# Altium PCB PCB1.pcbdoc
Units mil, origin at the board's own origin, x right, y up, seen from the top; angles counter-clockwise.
Board outline 3800 x 2700 mil, 2 copper layers (Top Layer, Bottom Layer), stack 62.2 mil thick; 15 components, 11 nets, 84 pads, 8 vias.
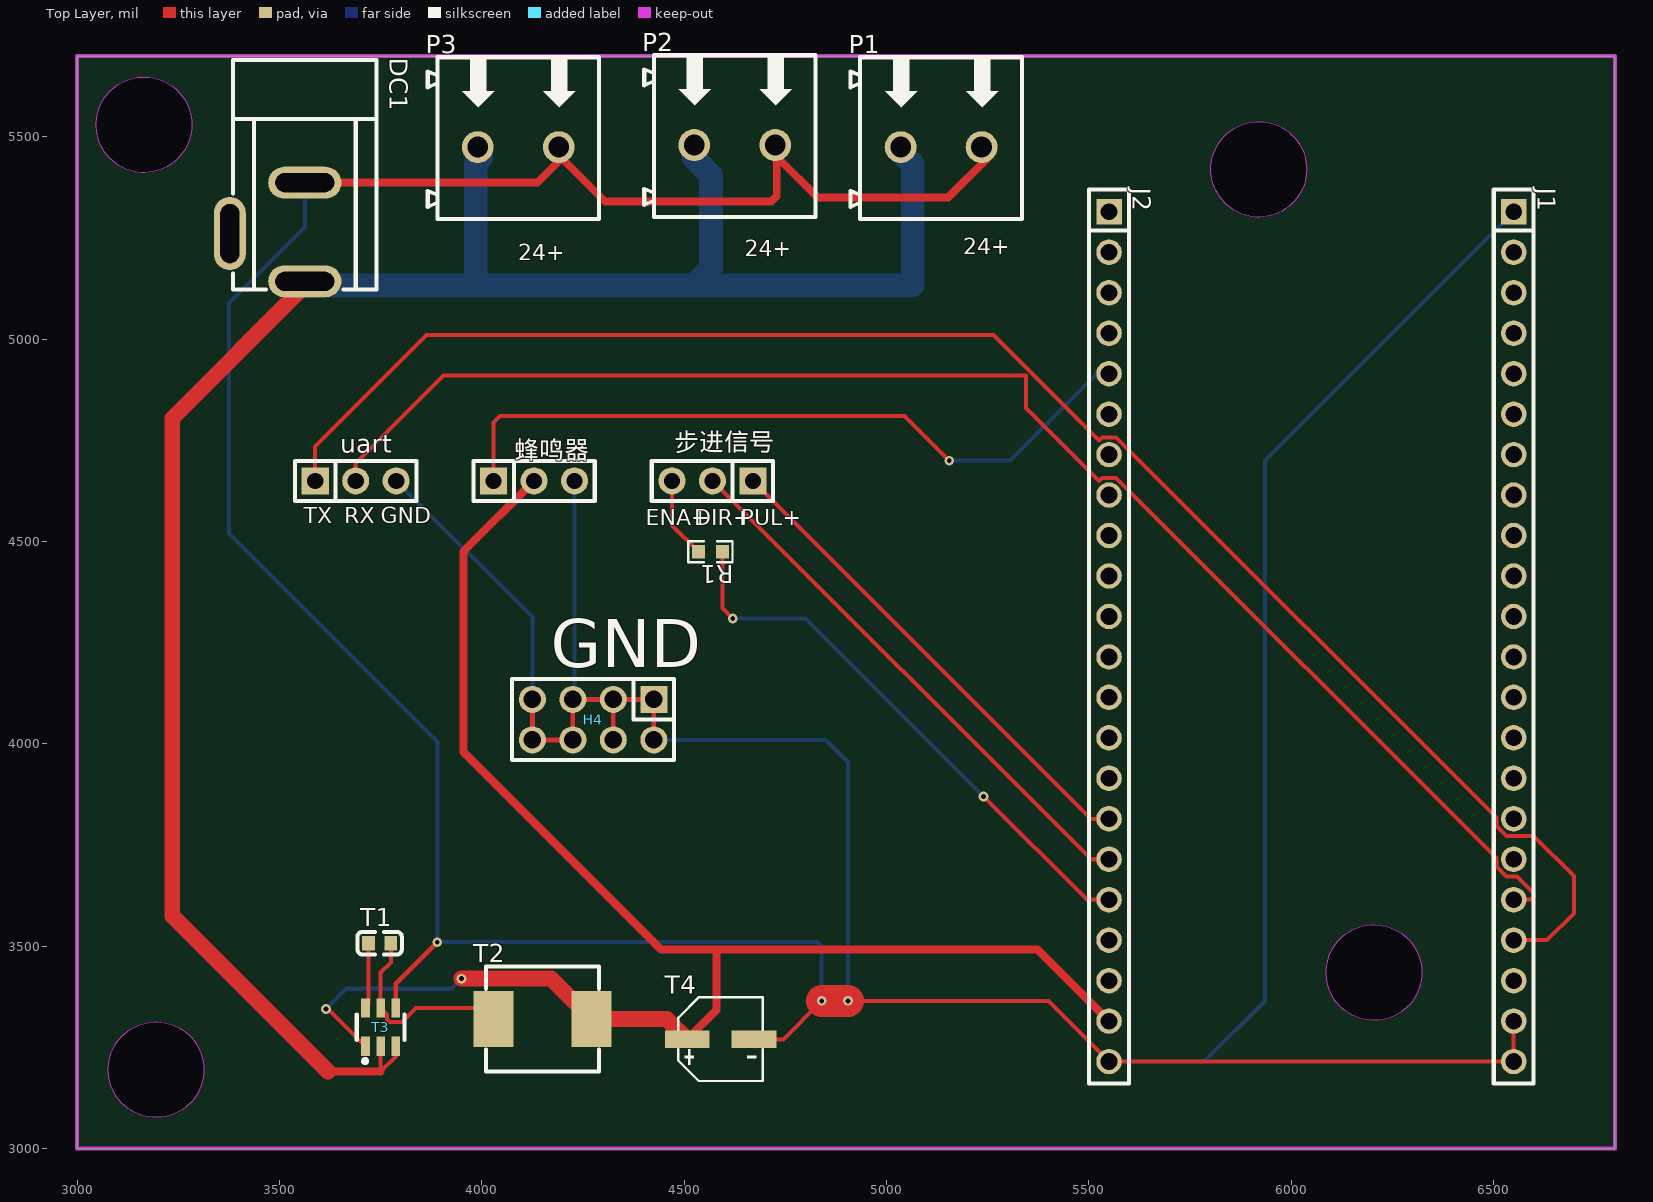
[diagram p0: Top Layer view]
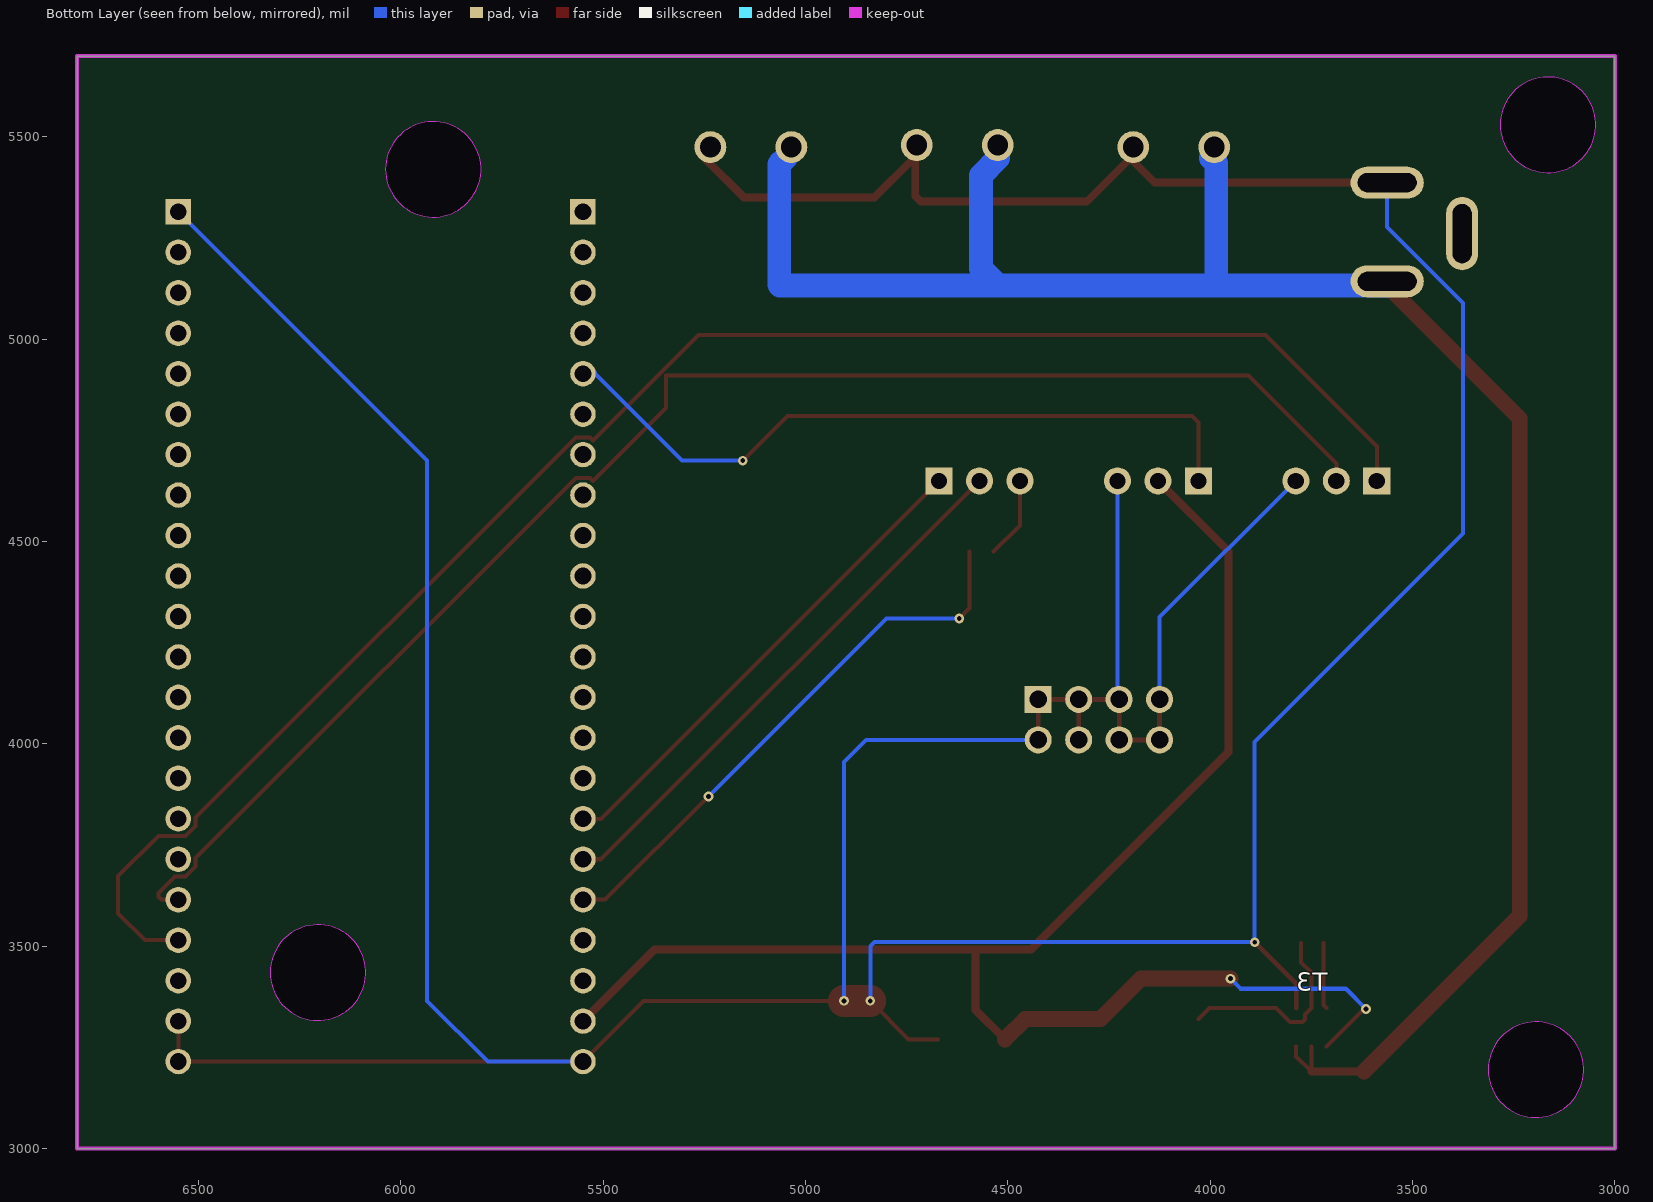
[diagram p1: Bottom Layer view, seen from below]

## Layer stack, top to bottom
Top Solder Mask Layer: solder mask 0.4, Dk 3.3
Top Layer: signal copper 1.4
Dielectric1: surface 59.4, FR4, Dk 4.5
Bottom Layer: signal copper 1.4
Bottom Solder Mask Layer: solder mask 0.4, Dk 3.3

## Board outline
3000,5700 3000,3000 6800,3000 6800,5700
cut-out: 3283.1,5530 3282.7,5520.4 3281.5,5510.8 3279.6,5501.4 3276.9,5492.1 3273.4,5483.1 3269.2,5474.5 3264.4,5466.1 3258.8,5458.3 3252.7,5450.8 3245.9,5444 3238.6,5437.7 3230.9,5432 3222.7,5426.9 3214.1,5422.6 3205.1,5418.9 3196,5416 3186.6,5413.9 3177,5412.5 3167.4,5411.9 3157.8,5412.1 3148.2,5413.1 3138.7,5414.9 3129.4,5417.4 3120.4,5420.7 3111.6,5424.7 3103.2,5429.4 3095.2,5434.7 3087.7,5440.7 3080.6,5447.3 3074.2,5454.5 3068.3,5462.1 3063.1,5470.3 3058.6,5478.8 3054.8,5487.6 3051.7,5496.7 3049.3,5506.1 3047.8,5515.6 3047,5525.2 3047,5534.8 3047.8,5544.4 3049.3,5553.9 3051.7,5563.3 3054.8,5572.4 3058.6,5581.2 3063.1,5589.7 3068.3,5597.9 3074.2,5605.5 3080.6,5612.7 3087.7,5619.3 3095.2,5625.3 3103.2,5630.6 3111.6,5635.3 3120.4,5639.3 3129.4,5642.6 3138.7,5645.1 3148.2,5646.9 3157.8,5647.9 3167.4,5648.1 3177,5647.5 3186.6,5646.1 3196,5644 3205.1,5641.1 3214.1,5637.4 3222.7,5633.1 3230.9,5628 3238.6,5622.3 3245.9,5616 3252.7,5609.2 3258.8,5601.7 3264.4,5593.9 3269.2,5585.5 3273.4,5576.9 3276.9,5567.9 3279.6,5558.6 3281.5,5549.2 3282.7,5539.6
cut-out: 3313.1,3195 3312.7,3185.4 3311.5,3175.8 3309.6,3166.4 3306.9,3157.1 3303.4,3148.1 3299.2,3139.5 3294.4,3131.1 3288.8,3123.3 3282.7,3115.8 3275.9,3109 3268.6,3102.7 3260.9,3097 3252.7,3091.9 3244.1,3087.6 3235.1,3083.9 3226,3081 3216.6,3078.9 3207,3077.5 3197.4,3076.9 3187.8,3077.1 3178.2,3078.1 3168.7,3079.9 3159.4,3082.4 3150.4,3085.7 3141.6,3089.7 3133.2,3094.4 3125.2,3099.7 3117.7,3105.7 3110.6,3112.3 3104.2,3119.5 3098.3,3127.1 3093.1,3135.3 3088.6,3143.8 3084.8,3152.6 3081.7,3161.7 3079.3,3171.1 3077.8,3180.6 3077,3190.2 3077,3199.8 3077.8,3209.4 3079.3,3218.9 3081.7,3228.3 3084.8,3237.4 3088.6,3246.2 3093.1,3254.7 3098.3,3262.9 3104.2,3270.5 3110.6,3277.7 3117.7,3284.3 3125.2,3290.3 3133.2,3295.6 3141.6,3300.3 3150.4,3304.3 3159.4,3307.6 3168.7,3310.1 3178.2,3311.9 3187.8,3312.9 3197.4,3313.1 3207,3312.5 3216.6,3311.1 3226,3309 3235.1,3306.1 3244.1,3302.4 3252.7,3298.1 3260.9,3293 3268.6,3287.3 3275.9,3281 3282.7,3274.2 3288.8,3266.7 3294.4,3258.9 3299.2,3250.5 3303.4,3241.9 3306.9,3232.9 3309.6,3223.6 3311.5,3214.2 3312.7,3204.6
cut-out: 6323.1,3435 6322.7,3425.4 6321.5,3415.8 6319.6,3406.4 6316.9,3397.1 6313.4,3388.1 6309.2,3379.5 6304.4,3371.1 6298.8,3363.3 6292.7,3355.8 6285.9,3349 6278.6,3342.7 6270.9,3337 6262.7,3331.9 6254.1,3327.6 6245.1,3323.9 6236,3321 6226.6,3318.9 6217,3317.5 6207.4,3316.9 6197.8,3317.1 6188.2,3318.1 6178.7,3319.9 6169.4,3322.4 6160.4,3325.7 6151.6,3329.7 6143.2,3334.4 6135.2,3339.7 6127.7,3345.7 6120.6,3352.3 6114.2,3359.5 6108.3,3367.1 6103.1,3375.3 6098.6,3383.8 6094.8,3392.6 6091.7,3401.7 6089.3,3411.1 6087.8,3420.6 6087,3430.2 6087,3439.8 6087.8,3449.4 6089.3,3458.9 6091.7,3468.3 6094.8,3477.4 6098.6,3486.2 6103.1,3494.7 6108.3,3502.9 6114.2,3510.5 6120.6,3517.7 6127.7,3524.3 6135.2,3530.3 6143.2,3535.6 6151.6,3540.3 6160.4,3544.3 6169.4,3547.6 6178.7,3550.1 6188.2,3551.9 6197.8,3552.9 6207.4,3553.1 6217,3552.5 6226.6,3551.1 6236,3549 6245.1,3546.1 6254.1,3542.4 6262.7,3538.1 6270.9,3533 6278.6,3527.3 6285.9,3521 6292.7,3514.2 6298.8,3506.7 6304.4,3498.9 6309.2,3490.5 6313.4,3481.9 6316.9,3472.9 6319.6,3463.6 6321.5,3454.2 6322.7,3444.6
cut-out: 6038.1,5420 6037.7,5410.4 6036.5,5400.8 6034.6,5391.4 6031.9,5382.1 6028.4,5373.1 6024.2,5364.5 6019.4,5356.1 6013.8,5348.3 6007.7,5340.8 6000.9,5334 5993.6,5327.7 5985.9,5322 5977.7,5316.9 5969.1,5312.6 5960.1,5308.9 5951,5306 5941.6,5303.9 5932,5302.5 5922.4,5301.9 5912.8,5302.1 5903.2,5303.1 5893.7,5304.9 5884.4,5307.4 5875.4,5310.7 5866.6,5314.7 5858.2,5319.4 5850.2,5324.7 5842.7,5330.7 5835.6,5337.3 5829.2,5344.5 5823.3,5352.1 5818.1,5360.3 5813.6,5368.8 5809.8,5377.6 5806.7,5386.7 5804.3,5396.1 5802.8,5405.6 5802,5415.2 5802,5424.8 5802.8,5434.4 5804.3,5443.9 5806.7,5453.3 5809.8,5462.4 5813.6,5471.2 5818.1,5479.7 5823.3,5487.9 5829.2,5495.5 5835.6,5502.7 5842.7,5509.3 5850.2,5515.3 5858.2,5520.6 5866.6,5525.3 5875.4,5529.3 5884.4,5532.6 5893.7,5535.1 5903.2,5536.9 5912.8,5537.9 5922.4,5538.1 5932,5537.5 5941.6,5536.1 5951,5534 5960.1,5531.1 5969.1,5527.4 5977.7,5523.1 5985.9,5518 5993.6,5512.3 6000.9,5506 6007.7,5499.2 6013.8,5491.7 6019.4,5483.9 6024.2,5475.5 6028.4,5466.9 6031.9,5457.9 6034.6,5448.6 6036.5,5439.2 6037.7,5429.6

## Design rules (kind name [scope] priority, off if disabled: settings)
BoardOutlineClearance copperThickness1oz [All] p0: genericclearance=10 ignorepadtopadclearanceinfootprint=FALSE except(0: Arc-SplitContinuation Track-SplitContinuation SMDPad-SplitContinuation THPad-SplitContinuation Via-SplitContinuation Fill-SplitContinuation Poly-SplitContinuation Region-SplitContinuation Text-SplitContinuation)
BoardOutlineClearance copperThickness2oz [All] p0: genericclearance=10 ignorepadtopadclearanceinfootprint=FALSE except(0: Arc-SplitContinuation Track-SplitContinuation SMDPad-SplitContinuation THPad-SplitContinuation Via-SplitContinuation Fill-SplitContinuation Poly-SplitContinuation Region-SplitContinuation Text-SplitContinuation)
BoardOutlineClearance otherClearance [All] p0: genericclearance=10 ignorepadtopadclearanceinfootprint=FALSE except(0: Arc-SplitContinuation Track-SplitContinuation SMDPad-SplitContinuation THPad-SplitContinuation Via-SplitContinuation Fill-SplitContinuation Poly-SplitContinuation Region-SplitContinuation Text-SplitContinuation)
Clearance copperThickness1oz [All] p1: gap=7 ignorepadtopadclearanceinfootprint=FALSE
Clearance copperThickness2oz [All] p1: gap=7 ignorepadtopadclearanceinfootprint=FALSE
Clearance otherClearance [All] p1: gap=7 ignorepadtopadclearanceinfootprint=FALSE
DiffPairsRouting differentialPair [All] p1: maxuncoupledlength=10 minlimit=6 maxlimit=Infinity mostfreqgap=6 toplayer_minwidth=5 toplayer_prefwidth=10 toplayer_maxwidth=100 bottomlayer_minwidth=5 bottomlayer_prefwidth=10 bottomlayer_maxwidth=100
PasteMaskExpansion pasteMaskExpansion [All] p1: expansion=0
PlaneConnect innerPlane [All] p1: planeconnectstyle=Relief reliefexpansion=20 reliefentries=4 reliefconductorwidth=10 reliefairgap=10
PolygonConnect copperRegion [All] p1: connectstyle=Relief reliefentries=4 reliefconductorwidth=10 polygonreliefangle="90 Angle" airgapwidth=10
RoutingVias viaSize [All] p1: viastyle="Through Hole" holewidth=12.0078 minholewidth=11.811 maxholewidth=248.0314 width=12.0078 minwidth=11.811 maxwidth=248.0314
SolderMaskExpansion solderMaskExpansion [IsVia] p1: useseparateexpansions=TRUE expansion=-1000 expansionbottom=-1000
SolderMaskExpansion solderMaskExpansion [All] p2: useseparateexpansions=TRUE expansion=2 expansionbottom=2
Width copperThickness1oz [All] p1: maxlimit=100 minlimit=5 preferedwidth=10
Width copperThickness2oz [All] p1: maxlimit=100 minlimit=8 preferedwidth=10

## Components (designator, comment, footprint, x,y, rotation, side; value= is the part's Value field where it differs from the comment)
DC1 "DC005" DC-IN-TH_DC005 3470,5265 r270 top
H4 "PZ254V-12-8P" HDR-TH_8P-P2.54-V-M-R2-C4-S2.54 4275,4060 r180 top
J1 "HC-PZ254-11.5L-1x22PZ" HDR-TH_22P-P2.54-V-M 6550,4265 r270 top
J2 "HC-PZ254-11.5L-1x22PZ" HDR-TH_22P-P2.54-V-M 5550,4265 r270 top
P1 "WJ500V-5.08-2P" CONN-TH_2P-P5.00_WJ500V-5.08-2P 5135,5475 r0 top
P2 "WJ500V-5.08-2P" CONN-TH_2P-P5.00_WJ500V-5.08-2P 4625,5480 r0 top
P3 "WJ500V-5.08-2P" CONN-TH_2P-P5.00_WJ500V-5.08-2P 4090,5475 r0 top
R1 "4.7kΩ" R0603 4565,4475 r180 top
T1 "10uF" C0603 3747.6,3507.6 r180 top
T2 "33uH" IND-SMD_L7.0-W6.6_FXL0650 4150,3320 r0 top
T3 "AP63205WU-7" TSOT-23-6_L2.9-W1.6-P0.95-LS2.8-BL 3750,3300 r0 top
T4 "22U25V-5*5.4mm" CAP-SMD_BD5.0-L5.3-W5.3-LS6.0-FD 4590,3270 r0 top
uart "PZ254V-11-03P" HDR-TH_3P-P2.54-V-M_PZ254V-11-03P 3688.3,4650 r0 top
步进信号 "PZ254V-11-03P" HDR-TH_3P-P2.54-V-M_PZ254V-11-03P 4570,4650 r180 top
蜂鸣器 "PZ254V-11-03P" HDR-TH_3P-P2.54-V-M_PZ254V-11-03P 4129.1,4650 r0 top

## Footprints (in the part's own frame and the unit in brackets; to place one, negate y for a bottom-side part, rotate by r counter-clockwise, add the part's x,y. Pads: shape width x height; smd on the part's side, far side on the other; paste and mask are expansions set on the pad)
C0603 [mil]
  rect 31.5x35.4 smd: 1(-27.5,0) 2(27.6,0)
  silkscreen extent -55,-28 55,28
CAP-SMD_BD5.0-L5.3-W5.3-LS6.0-FD [mil]
  rect 110.2x43.3 smd: 1(-82.7,0) 2(82.7,0)
  silkscreen extent -105,-103 105,104
CONN-TH_2P-P5.00_WJ500V-5.08-2P [mil]
  round 78.7 hole 51.2: 1(-100,0) 2(100,0)
  silkscreen extent -224,-178 200,222
DC-IN-TH_DC005 [mil]
  oval 78.7x181.1 hole 47.2 slot 145.7 at 90 deg: 1(122,92.5) 2(-122,92.5)
  oval 181.1x78.7 hole 47.2 slot 145.7 at 0 deg: 3(3.9,-92.5)
  silkscreen extent -425,-85 142,270
HDR-TH_3P-P2.54-V-M_PZ254V-11-03P [mil]
  rect 66.9x66.9 hole 40.2: 1(-100,0)
  round 66.9 hole 40.2: 2(0,0) 3(100,0)
  silkscreen extent -150,-49 150,49
HDR-TH_8P-P2.54-V-M-R2-C4-S2.54 [mil]
  rect 66.9x66.9 hole 43.3: 1(-150,-50)
  round 66.9 hole 43.3: 2(-150,50) 3(-50,-50) 4(-50,50) 5(50,-50) 6(50,50) 7(150,-50) 8(150,50)
  silkscreen extent -200,-100 200,100
HDR-TH_22P-P2.54-V-M [mil]
  rect 63x63 hole 41.3: 1(-1050,0)
  round 63 hole 41.3: 2(-950,0) 3(-850,0) 4(-750,0) 5(-650,0) 6(-550,0) 7(-450,0) 8(-350,0) 9(-250,0) 10(-150,0) 11(-50,0) 12(50,0) 13(150,0) 14(250,0) 15(350,0) 16(450,0) 17(550,0) 18(650,0) 19(750,0) 20(850,0) 21(950,0) 22(1050,0)
  silkscreen extent -1105,-49 1105,49
IND-SMD_L7.0-W6.6_FXL0650 [mil]
  rect 99.4x137.8 smd: 1(-121.2,0) 2(121.2,0)
  silkscreen extent -140,-130 140,130
R0603 [mil]
  rect 31.8x34 smd paste-3937 mask+2: 1(-29.7,0) 2(29.7,0)
  silkscreen extent -54,-26 54,26
TSOT-23-6_L2.9-W1.6-P0.95-LS2.8-BL [mil]
  rect 21.7x47.2 smd paste+0 mask+2: 1(-37.4,-47.2) 2(0,-47.2) 3(37.4,-47.2) 4(37.4,47.2) 5(0,47.2) 6(-37.4,47.2)
  silkscreen extent -59,-89 59,32

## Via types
v1: diameter 24, hole 12, Top Layer to Bottom Layer, 8 vias

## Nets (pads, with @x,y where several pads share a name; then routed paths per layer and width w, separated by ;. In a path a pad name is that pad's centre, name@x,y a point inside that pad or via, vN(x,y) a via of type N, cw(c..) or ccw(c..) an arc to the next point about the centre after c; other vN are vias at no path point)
$1N8: T1.2 T3.6 | length 163.5
  Top Layer w10: T3.6 3720,3354.6 T1.2
$1N9: T1.1 T2.1 T3.5 | length 496.9
  Top Layer w10: T1.1 3775.1,3460.1 3750,3435 T3.5 3765.6,3331.7 3765.6,3319.1 3772,3312.6 3802.8,3312.6 3837.4,3347.2 4001.6,3347.2 T2.1
+5V: J2.21 T2.2 T3.1 T4.1 蜂鸣器.2 | length 3989
  Top Layer w10: v1(3615,3345) 3620.3,3345 T3.1
  Top Layer w19.7: 蜂鸣器.2 3955,4475.9 3955,3980 4442.9,3492.1 4587.1,3492.1 ; T4.1 4580,3342.7 4580,3485 4587.1,3492.1 ; J2.21 5372.9,3492.1 4587.1,3492.1
  Top Layer w39.4: v1(3950,3420) 4171.2,3420 T2.2 4457.3,3320 T4.1
  Bottom Layer w10: v1(3615,3345) 3665,3395 3925,3395 v1(3950,3420)
DIR+: J2.17 步进信号.2 | length 1367.3
  Top Layer w10: 步进信号.2 5505,3715 J2.17
ENA: J2.18 R1.1 R1.2 步进信号.3 | length 1600.4
  Top Layer w10: 步进信号.3 4470,4540.3 R1.2 ; R1.1 4594.7,4335.3 v1(4620,4310) ; v1(5240,3870) 5495,3615 J2.18 J2.18@5550,3610
  Bottom Layer w10: v1(4620,4310) 4800,4310 v1(5240,3870)
GND: DC1.2 DC1.3 H4.1 H4.2 H4.3 H4.4 H4.5 H4.6 H4.7 H4.8 J1.1 J1.21 J1.22 J2.22 P1.2 P2.2 P3.2 T3.4 T4.2 uart.3 蜂鸣器.3 | length 13151.6
  Top Layer w10: T4.2 4745,3270 v1(4840,3365) ; v1(4905,3365) 5400,3365 J2.22 J1.22 J1.21
  Top Layer w11.8: T3.4 3787.4,3407.4 v1(3890,3510) ; H4.7 H4.8 H4.6 H4.5 H4.3 ; H4.4 H4.3 ; H4.2 H4.1 H4.3
  Top Layer w19.7: DC1.2 4137.1,5387 4197.7,5447.6 4305.3,5340 4715,5340 4728.9,5353.9 4728.9,5442.6 4723.9,5447.6 4732.4,5447.6 4830,5350 5152.4,5350 P1.2@5250,5447.6
  Top Layer w78.7: v1(4840,3365) v1(4905,3365)
  Bottom Layer w10: DC1.2 3562.5,5277.5 3375,5090 3375,4520 3890,4005 v1(3890,3510) 4830,3510 4840,3500 v1(4840,3365) ; uart.3 4125,4313.3 H4.7 ; H4.5 4229.1,4114.1 蜂鸣器.3 ; H4.2 4850,4010 4905,3955 v1(4905,3365) ; J2.22 5785,3215 5935,3365 5935,4700 J1.1
PUL+: J2.16 步进信号.1 | length 1225.9
  Top Layer w10: 步进信号.1 5505,3815 J2.16
RX: J1.18 uart.2 | length 3699.3
  Top Layer w10: uart.2 3688.3,4693.5 3904.8,4910 5345,4910 5345,4829.9 5524.9,4650 5532.4,4657.5 5567.6,4657.5 6507.5,3717.6 6507.5,3697.4 6532.4,3672.5 6558.1,3672.5 6598.6,3632.1 6598.6,3622.1 6591.5,3615 J1.18
TX: J1.19 uart.1 | length 4149.4
  Top Layer w10: uart.1 3588.3,4734.9 3863.4,5010 5264.9,5010 5524.9,4750 5532.4,4757.5 5567.6,4757.5 6507.5,3817.6 6507.5,3797.4 6532.4,3772.5 6599.5,3772.5 6698.6,3673.5 6698.6,3580.6 6632.9,3515 J1.19
VCC: DC1.1 P1.1 P2.1 P3.1 T3.2 T3.3 | length 5003
  Top Layer w10: T3.2 3750,3190 3787.4,3227.4 T3.3
  Top Layer w19.7: 3620,3190 3750,3190
  Top Layer w39.4: DC1.1@3563.9,5133 3235,4804.1 3235,3575 3620,3190
  Bottom Layer w59.1: DC1.1@3563.9,5133 3978,5133 ; P3.1@3997.7,5447.6 3985,5434.9 3985,5140 3978,5133 ; P2.1@4523.9,5447.6 4566.8,5404.7 4566.8,5174.7 4525,5133 ; P1.1@5050,5447.6 5065,5432.6 5065,5135 5063,5133 4525,5133 ; 3978,5133 4525,5133
蜂鸣器: J2.5 蜂鸣器.1 | length 1813.2
  Top Layer w10: 蜂鸣器.1 4029.1,4794.1 4045,4810 5045,4810 v1(5155,4700)
  Bottom Layer w10: v1(5155,4700) 5305,4700 J2.5@5520,4915 ; J2.5 J2.5@5522.9,4915 ; J2.5@5520,4915 5520,4917.9 J2.5@5522.9,4915 ; J2.5@5520,4915 J2.5@5522.9,4915
pads on no net: J1.2 J1.3 J1.4 J1.5 J1.6 J1.7 J1.8 J1.9 J1.10 J1.11 J1.12 J1.13 J1.14 J1.15 J1.16 J1.17 J1.20 J2.1 J2.2 J2.3 J2.4 J2.6 J2.7 J2.8 J2.9 J2.10 J2.11 J2.12 J2.13 J2.14 J2.15 J2.19 J2.20

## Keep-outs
Board Outline Layer:
  region: 3283.1,5530 3282.7,5520.4 3281.5,5510.8 3279.6,5501.4 3276.9,5492.1 3273.4,5483.1 3269.2,5474.5 3264.4,5466.1 3258.8,5458.3 3252.7,5450.8 3245.9,5444 3238.6,5437.7 3230.9,5432 3222.7,5426.9 3214.1,5422.6 3205.1,5418.9 3196,5416 3186.6,5413.9 3177,5412.5 3167.4,5411.9 3157.8,5412.1 3148.2,5413.1 3138.7,5414.9 3129.4,5417.4 3120.4,5420.7 3111.6,5424.7 3103.2,5429.4 3095.2,5434.7 3087.7,5440.7 3080.6,5447.3 3074.2,5454.5 3068.3,5462.1 3063.1,5470.3 3058.6,5478.8 3054.8,5487.6 3051.7,5496.7 3049.3,5506.1 3047.8,5515.6 3047,5525.2 3047,5534.8 3047.8,5544.4 3049.3,5553.9 3051.7,5563.3 3054.8,5572.4 3058.6,5581.2 3063.1,5589.7 3068.3,5597.9 3074.2,5605.5 3080.6,5612.7 3087.7,5619.3 3095.2,5625.3 3103.2,5630.6 3111.6,5635.3 3120.4,5639.3 3129.4,5642.6 3138.7,5645.1 3148.2,5646.9 3157.8,5647.9 3167.4,5648.1 3177,5647.5 3186.6,5646.1 3196,5644 3205.1,5641.1 3214.1,5637.4 3222.7,5633.1 3230.9,5628 3238.6,5622.3 3245.9,5616 3252.7,5609.2 3258.8,5601.7 3264.4,5593.9 3269.2,5585.5 3273.4,5576.9 3276.9,5567.9 3279.6,5558.6 3281.5,5549.2 3282.7,5539.6
  region: 3283.1,5530 3282.7,5520.4 3281.5,5510.8 3279.6,5501.4 3276.9,5492.1 3273.4,5483.1 3269.2,5474.5 3264.4,5466.1 3258.8,5458.3 3252.7,5450.8 3245.9,5444 3238.6,5437.7 3230.9,5432 3222.7,5426.9 3214.1,5422.6 3205.1,5418.9 3196,5416 3186.6,5413.9 3177,5412.5 3167.4,5411.9 3157.8,5412.1 3148.2,5413.1 3138.7,5414.9 3129.4,5417.4 3120.4,5420.7 3111.6,5424.7 3103.2,5429.4 3095.2,5434.7 3087.7,5440.7 3080.6,5447.3 3074.2,5454.5 3068.3,5462.1 3063.1,5470.3 3058.6,5478.8 3054.8,5487.6 3051.7,5496.7 3049.3,5506.1 3047.8,5515.6 3047,5525.2 3047,5534.8 3047.8,5544.4 3049.3,5553.9 3051.7,5563.3 3054.8,5572.4 3058.6,5581.2 3063.1,5589.7 3068.3,5597.9 3074.2,5605.5 3080.6,5612.7 3087.7,5619.3 3095.2,5625.3 3103.2,5630.6 3111.6,5635.3 3120.4,5639.3 3129.4,5642.6 3138.7,5645.1 3148.2,5646.9 3157.8,5647.9 3167.4,5648.1 3177,5647.5 3186.6,5646.1 3196,5644 3205.1,5641.1 3214.1,5637.4 3222.7,5633.1 3230.9,5628 3238.6,5622.3 3245.9,5616 3252.7,5609.2 3258.8,5601.7 3264.4,5593.9 3269.2,5585.5 3273.4,5576.9 3276.9,5567.9 3279.6,5558.6 3281.5,5549.2 3282.7,5539.6
  region: 3313.1,3195 3312.7,3185.4 3311.5,3175.8 3309.6,3166.4 3306.9,3157.1 3303.4,3148.1 3299.2,3139.5 3294.4,3131.1 3288.8,3123.3 3282.7,3115.8 3275.9,3109 3268.6,3102.7 3260.9,3097 3252.7,3091.9 3244.1,3087.6 3235.1,3083.9 3226,3081 3216.6,3078.9 3207,3077.5 3197.4,3076.9 3187.8,3077.1 3178.2,3078.1 3168.7,3079.9 3159.4,3082.4 3150.4,3085.7 3141.6,3089.7 3133.2,3094.4 3125.2,3099.7 3117.7,3105.7 3110.6,3112.3 3104.2,3119.5 3098.3,3127.1 3093.1,3135.3 3088.6,3143.8 3084.8,3152.6 3081.7,3161.7 3079.3,3171.1 3077.8,3180.6 3077,3190.2 3077,3199.8 3077.8,3209.4 3079.3,3218.9 3081.7,3228.3 3084.8,3237.4 3088.6,3246.2 3093.1,3254.7 3098.3,3262.9 3104.2,3270.5 3110.6,3277.7 3117.7,3284.3 3125.2,3290.3 3133.2,3295.6 3141.6,3300.3 3150.4,3304.3 3159.4,3307.6 3168.7,3310.1 3178.2,3311.9 3187.8,3312.9 3197.4,3313.1 3207,3312.5 3216.6,3311.1 3226,3309 3235.1,3306.1 3244.1,3302.4 3252.7,3298.1 3260.9,3293 3268.6,3287.3 3275.9,3281 3282.7,3274.2 3288.8,3266.7 3294.4,3258.9 3299.2,3250.5 3303.4,3241.9 3306.9,3232.9 3309.6,3223.6 3311.5,3214.2 3312.7,3204.6
  region: 3313.1,3195 3312.7,3185.4 3311.5,3175.8 3309.6,3166.4 3306.9,3157.1 3303.4,3148.1 3299.2,3139.5 3294.4,3131.1 3288.8,3123.3 3282.7,3115.8 3275.9,3109 3268.6,3102.7 3260.9,3097 3252.7,3091.9 3244.1,3087.6 3235.1,3083.9 3226,3081 3216.6,3078.9 3207,3077.5 3197.4,3076.9 3187.8,3077.1 3178.2,3078.1 3168.7,3079.9 3159.4,3082.4 3150.4,3085.7 3141.6,3089.7 3133.2,3094.4 3125.2,3099.7 3117.7,3105.7 3110.6,3112.3 3104.2,3119.5 3098.3,3127.1 3093.1,3135.3 3088.6,3143.8 3084.8,3152.6 3081.7,3161.7 3079.3,3171.1 3077.8,3180.6 3077,3190.2 3077,3199.8 3077.8,3209.4 3079.3,3218.9 3081.7,3228.3 3084.8,3237.4 3088.6,3246.2 3093.1,3254.7 3098.3,3262.9 3104.2,3270.5 3110.6,3277.7 3117.7,3284.3 3125.2,3290.3 3133.2,3295.6 3141.6,3300.3 3150.4,3304.3 3159.4,3307.6 3168.7,3310.1 3178.2,3311.9 3187.8,3312.9 3197.4,3313.1 3207,3312.5 3216.6,3311.1 3226,3309 3235.1,3306.1 3244.1,3302.4 3252.7,3298.1 3260.9,3293 3268.6,3287.3 3275.9,3281 3282.7,3274.2 3288.8,3266.7 3294.4,3258.9 3299.2,3250.5 3303.4,3241.9 3306.9,3232.9 3309.6,3223.6 3311.5,3214.2 3312.7,3204.6
  region: 6323.1,3435 6322.7,3425.4 6321.5,3415.8 6319.6,3406.4 6316.9,3397.1 6313.4,3388.1 6309.2,3379.5 6304.4,3371.1 6298.8,3363.3 6292.7,3355.8 6285.9,3349 6278.6,3342.7 6270.9,3337 6262.7,3331.9 6254.1,3327.6 6245.1,3323.9 6236,3321 6226.6,3318.9 6217,3317.5 6207.4,3316.9 6197.8,3317.1 6188.2,3318.1 6178.7,3319.9 6169.4,3322.4 6160.4,3325.7 6151.6,3329.7 6143.2,3334.4 6135.2,3339.7 6127.7,3345.7 6120.6,3352.3 6114.2,3359.5 6108.3,3367.1 6103.1,3375.3 6098.6,3383.8 6094.8,3392.6 6091.7,3401.7 6089.3,3411.1 6087.8,3420.6 6087,3430.2 6087,3439.8 6087.8,3449.4 6089.3,3458.9 6091.7,3468.3 6094.8,3477.4 6098.6,3486.2 6103.1,3494.7 6108.3,3502.9 6114.2,3510.5 6120.6,3517.7 6127.7,3524.3 6135.2,3530.3 6143.2,3535.6 6151.6,3540.3 6160.4,3544.3 6169.4,3547.6 6178.7,3550.1 6188.2,3551.9 6197.8,3552.9 6207.4,3553.1 6217,3552.5 6226.6,3551.1 6236,3549 6245.1,3546.1 6254.1,3542.4 6262.7,3538.1 6270.9,3533 6278.6,3527.3 6285.9,3521 6292.7,3514.2 6298.8,3506.7 6304.4,3498.9 6309.2,3490.5 6313.4,3481.9 6316.9,3472.9 6319.6,3463.6 6321.5,3454.2 6322.7,3444.6
  region: 6323.1,3435 6322.7,3425.4 6321.5,3415.8 6319.6,3406.4 6316.9,3397.1 6313.4,3388.1 6309.2,3379.5 6304.4,3371.1 6298.8,3363.3 6292.7,3355.8 6285.9,3349 6278.6,3342.7 6270.9,3337 6262.7,3331.9 6254.1,3327.6 6245.1,3323.9 6236,3321 6226.6,3318.9 6217,3317.5 6207.4,3316.9 6197.8,3317.1 6188.2,3318.1 6178.7,3319.9 6169.4,3322.4 6160.4,3325.7 6151.6,3329.7 6143.2,3334.4 6135.2,3339.7 6127.7,3345.7 6120.6,3352.3 6114.2,3359.5 6108.3,3367.1 6103.1,3375.3 6098.6,3383.8 6094.8,3392.6 6091.7,3401.7 6089.3,3411.1 6087.8,3420.6 6087,3430.2 6087,3439.8 6087.8,3449.4 6089.3,3458.9 6091.7,3468.3 6094.8,3477.4 6098.6,3486.2 6103.1,3494.7 6108.3,3502.9 6114.2,3510.5 6120.6,3517.7 6127.7,3524.3 6135.2,3530.3 6143.2,3535.6 6151.6,3540.3 6160.4,3544.3 6169.4,3547.6 6178.7,3550.1 6188.2,3551.9 6197.8,3552.9 6207.4,3553.1 6217,3552.5 6226.6,3551.1 6236,3549 6245.1,3546.1 6254.1,3542.4 6262.7,3538.1 6270.9,3533 6278.6,3527.3 6285.9,3521 6292.7,3514.2 6298.8,3506.7 6304.4,3498.9 6309.2,3490.5 6313.4,3481.9 6316.9,3472.9 6319.6,3463.6 6321.5,3454.2 6322.7,3444.6
  region: 6038.1,5420 6037.7,5410.4 6036.5,5400.8 6034.6,5391.4 6031.9,5382.1 6028.4,5373.1 6024.2,5364.5 6019.4,5356.1 6013.8,5348.3 6007.7,5340.8 6000.9,5334 5993.6,5327.7 5985.9,5322 5977.7,5316.9 5969.1,5312.6 5960.1,5308.9 5951,5306 5941.6,5303.9 5932,5302.5 5922.4,5301.9 5912.8,5302.1 5903.2,5303.1 5893.7,5304.9 5884.4,5307.4 5875.4,5310.7 5866.6,5314.7 5858.2,5319.4 5850.2,5324.7 5842.7,5330.7 5835.6,5337.3 5829.2,5344.5 5823.3,5352.1 5818.1,5360.3 5813.6,5368.8 5809.8,5377.6 5806.7,5386.7 5804.3,5396.1 5802.8,5405.6 5802,5415.2 5802,5424.8 5802.8,5434.4 5804.3,5443.9 5806.7,5453.3 5809.8,5462.4 5813.6,5471.2 5818.1,5479.7 5823.3,5487.9 5829.2,5495.5 5835.6,5502.7 5842.7,5509.3 5850.2,5515.3 5858.2,5520.6 5866.6,5525.3 5875.4,5529.3 5884.4,5532.6 5893.7,5535.1 5903.2,5536.9 5912.8,5537.9 5922.4,5538.1 5932,5537.5 5941.6,5536.1 5951,5534 5960.1,5531.1 5969.1,5527.4 5977.7,5523.1 5985.9,5518 5993.6,5512.3 6000.9,5506 6007.7,5499.2 6013.8,5491.7 6019.4,5483.9 6024.2,5475.5 6028.4,5466.9 6031.9,5457.9 6034.6,5448.6 6036.5,5439.2 6037.7,5429.6
  region: 6038.1,5420 6037.7,5410.4 6036.5,5400.8 6034.6,5391.4 6031.9,5382.1 6028.4,5373.1 6024.2,5364.5 6019.4,5356.1 6013.8,5348.3 6007.7,5340.8 6000.9,5334 5993.6,5327.7 5985.9,5322 5977.7,5316.9 5969.1,5312.6 5960.1,5308.9 5951,5306 5941.6,5303.9 5932,5302.5 5922.4,5301.9 5912.8,5302.1 5903.2,5303.1 5893.7,5304.9 5884.4,5307.4 5875.4,5310.7 5866.6,5314.7 5858.2,5319.4 5850.2,5324.7 5842.7,5330.7 5835.6,5337.3 5829.2,5344.5 5823.3,5352.1 5818.1,5360.3 5813.6,5368.8 5809.8,5377.6 5806.7,5386.7 5804.3,5396.1 5802.8,5405.6 5802,5415.2 5802,5424.8 5802.8,5434.4 5804.3,5443.9 5806.7,5453.3 5809.8,5462.4 5813.6,5471.2 5818.1,5479.7 5823.3,5487.9 5829.2,5495.5 5835.6,5502.7 5842.7,5509.3 5850.2,5515.3 5858.2,5520.6 5866.6,5525.3 5875.4,5529.3 5884.4,5532.6 5893.7,5535.1 5903.2,5536.9 5912.8,5537.9 5922.4,5538.1 5932,5537.5 5941.6,5536.1 5951,5534 5960.1,5531.1 5969.1,5527.4 5977.7,5523.1 5985.9,5518 5993.6,5512.3 6000.9,5506 6007.7,5499.2 6013.8,5491.7 6019.4,5483.9 6024.2,5475.5 6028.4,5466.9 6031.9,5457.9 6034.6,5448.6 6036.5,5439.2 6037.7,5429.6
  lines w0.1: 3047,5525.2 3047.8,5515.6 3049.3,5506.1 3051.7,5496.7 3054.8,5487.6 3058.6,5478.8 3063.1,5470.3 3068.3,5462.1 3074.2,5454.5 3080.6,5447.3 3087.7,5440.7 3095.2,5434.7 3103.2,5429.4 3111.6,5424.7 3120.4,5420.7 3129.4,5417.4 3138.7,5414.9 3148.2,5413.1 3157.8,5412.1 3167.4,5411.9 3177,5412.5 3186.6,5413.9 3196,5416 3205.1,5418.9 3214.1,5422.6 3222.7,5426.9 3230.9,5432 3238.6,5437.7 3245.9,5444 3252.7,5450.8 3258.8,5458.3 3264.4,5466.1 3269.2,5474.5 3273.4,5483.1 3276.9,5492.1 3279.6,5501.4 3281.5,5510.8 3282.7,5520.4 3283.1,5530 3282.7,5539.6 3281.5,5549.2 3279.6,5558.6 3276.9,5567.9 3273.4,5576.9 3269.2,5585.5 3264.4,5593.9 3258.8,5601.7 3252.7,5609.2 3245.9,5616 3238.6,5622.3 3230.9,5628 3222.7,5633.1 3214.1,5637.4 3205.1,5641.1 3196,5644 3186.6,5646.1 3177,5647.5 3167.4,5648.1 3157.8,5647.9 3148.2,5646.9 3138.7,5645.1 3129.4,5642.6 3120.4,5639.3 3111.6,5635.3 3103.2,5630.6 3095.2,5625.3 3087.7,5619.3 3080.6,5612.7 3074.2,5605.5 3068.3,5597.9 3063.1,5589.7 3058.6,5581.2 3054.8,5572.4 3051.7,5563.3 3049.3,5553.9 3047.8,5544.4 3047,5534.8 3047,5525.2 ; 3077,3190.2 3077.8,3180.6 3079.3,3171.1 3081.7,3161.7 3084.8,3152.6 3088.6,3143.8 3093.1,3135.3 3098.3,3127.1 3104.2,3119.5 3110.6,3112.3 3117.7,3105.7 3125.2,3099.7 3133.2,3094.4 3141.6,3089.7 3150.4,3085.7 3159.4,3082.4 3168.7,3079.9 3178.2,3078.1 3187.8,3077.1 3197.4,3076.9 3207,3077.5 3216.6,3078.9 3226,3081 3235.1,3083.9 3244.1,3087.6 3252.7,3091.9 3260.9,3097 3268.6,3102.7 3275.9,3109 3282.7,3115.8 3288.8,3123.3 3294.4,3131.1 3299.2,3139.5 3303.4,3148.1 3306.9,3157.1 3309.6,3166.4 3311.5,3175.8 3312.7,3185.4 3313.1,3195 3312.7,3204.6 3311.5,3214.2 3309.6,3223.6 3306.9,3232.9 3303.4,3241.9 3299.2,3250.5 3294.4,3258.9 3288.8,3266.7 3282.7,3274.2 3275.9,3281 3268.6,3287.3 3260.9,3293 3252.7,3298.1 3244.1,3302.4 3235.1,3306.1 3226,3309 3216.6,3311.1 3207,3312.5 3197.4,3313.1 3187.8,3312.9 3178.2,3311.9 3168.7,3310.1 3159.4,3307.6 3150.4,3304.3 3141.6,3300.3 3133.2,3295.6 3125.2,3290.3 3117.7,3284.3 3110.6,3277.7 3104.2,3270.5 3098.3,3262.9 3093.1,3254.7 3088.6,3246.2 3084.8,3237.4 3081.7,3228.3 3079.3,3218.9 3077.8,3209.4 3077,3199.8 3077,3190.2 ; 5802,5415.2 5802.8,5405.6 5804.3,5396.1 5806.7,5386.7 5809.8,5377.6 5813.6,5368.8 5818.1,5360.3 5823.3,5352.1 5829.2,5344.5 5835.6,5337.3 5842.7,5330.7 5850.2,5324.7 5858.2,5319.4 5866.6,5314.7 5875.4,5310.7 5884.4,5307.4 5893.7,5304.9 5903.2,5303.1 5912.8,5302.1 5922.4,5301.9 5932,5302.5 5941.6,5303.9 5951,5306 5960.1,5308.9 5969.1,5312.6 5977.7,5316.9 5985.9,5322 5993.6,5327.7 6000.9,5334 6007.7,5340.8 6013.8,5348.3 6019.4,5356.1 6024.2,5364.5 6028.4,5373.1 6031.9,5382.1 6034.6,5391.4 6036.5,5400.8 6037.7,5410.4 6038.1,5420 6037.7,5429.6 6036.5,5439.2 6034.6,5448.6 6031.9,5457.9 6028.4,5466.9 6024.2,5475.5 6019.4,5483.9 6013.8,5491.7 6007.7,5499.2 6000.9,5506 5993.6,5512.3 5985.9,5518 5977.7,5523.1 5969.1,5527.4 5960.1,5531.1 5951,5534 5941.6,5536.1 5932,5537.5 5922.4,5538.1 5912.8,5537.9 5903.2,5536.9 5893.7,5535.1 5884.4,5532.6 5875.4,5529.3 5866.6,5525.3 5858.2,5520.6 5850.2,5515.3 5842.7,5509.3 5835.6,5502.7 5829.2,5495.5 5823.3,5487.9 5818.1,5479.7 5813.6,5471.2 5809.8,5462.4 5806.7,5453.3 5804.3,5443.9 5802.8,5434.4 5802,5424.8 5802,5415.2 ; 6087,3430.2 6087.8,3420.6 6089.3,3411.1 6091.7,3401.7 6094.8,3392.6 6098.6,3383.8 6103.1,3375.3 6108.3,3367.1 6114.2,3359.5 6120.6,3352.3 6127.7,3345.7 6135.2,3339.7 6143.2,3334.4 6151.6,3329.7 6160.4,3325.7 6169.4,3322.4 6178.7,3319.9 6188.2,3318.1 6197.8,3317.1 6207.4,3316.9 6217,3317.5 6226.6,3318.9 6236,3321 6245.1,3323.9 6254.1,3327.6 6262.7,3331.9 6270.9,3337 6278.6,3342.7 6285.9,3349 6292.7,3355.8 6298.8,3363.3 6304.4,3371.1 6309.2,3379.5 6313.4,3388.1 6316.9,3397.1 6319.6,3406.4 6321.5,3415.8 6322.7,3425.4 6323.1,3435 6322.7,3444.6 6321.5,3454.2 6319.6,3463.6 6316.9,3472.9 6313.4,3481.9 6309.2,3490.5 6304.4,3498.9 6298.8,3506.7 6292.7,3514.2 6285.9,3521 6278.6,3527.3 6270.9,3533 6262.7,3538.1 6254.1,3542.4 6245.1,3546.1 6236,3549 6226.6,3551.1 6217,3552.5 6207.4,3553.1 6197.8,3552.9 6188.2,3551.9 6178.7,3550.1 6169.4,3547.6 6160.4,3544.3 6151.6,3540.3 6143.2,3535.6 6135.2,3530.3 6127.7,3524.3 6120.6,3517.7 6114.2,3510.5 6108.3,3502.9 6103.1,3494.7 6098.6,3486.2 6094.8,3477.4 6091.7,3468.3 6089.3,3458.9 6087.8,3449.4 6087,3439.8 6087,3430.2
  lines w10: 3000,3000 3000,5700 6800,5700 6800,3000 3000,3000

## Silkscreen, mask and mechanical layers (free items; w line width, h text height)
Top Silkscreen Layer:
  text "24+" at 5190,5210 h39.4
  text "24+" at 4650,5205 h39.4
  text "24+" at 4090,5195 h39.4
  text "TX" at 3560,4545 h39.4
  text "RX" at 3660,4545 h39.4
  text "GND" at 3750,4545 h39.4
  text "ENA+" at 4405,4540 h39.4
  text "DIR+" at 4525,4540 h39.4
  text "PUL+" at 4640,4540 h39.4
  text "GND" at 4170,4190 h118.1
Mechanical Layer:
  drawing of 308 lines, arcs and shapes, not listed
